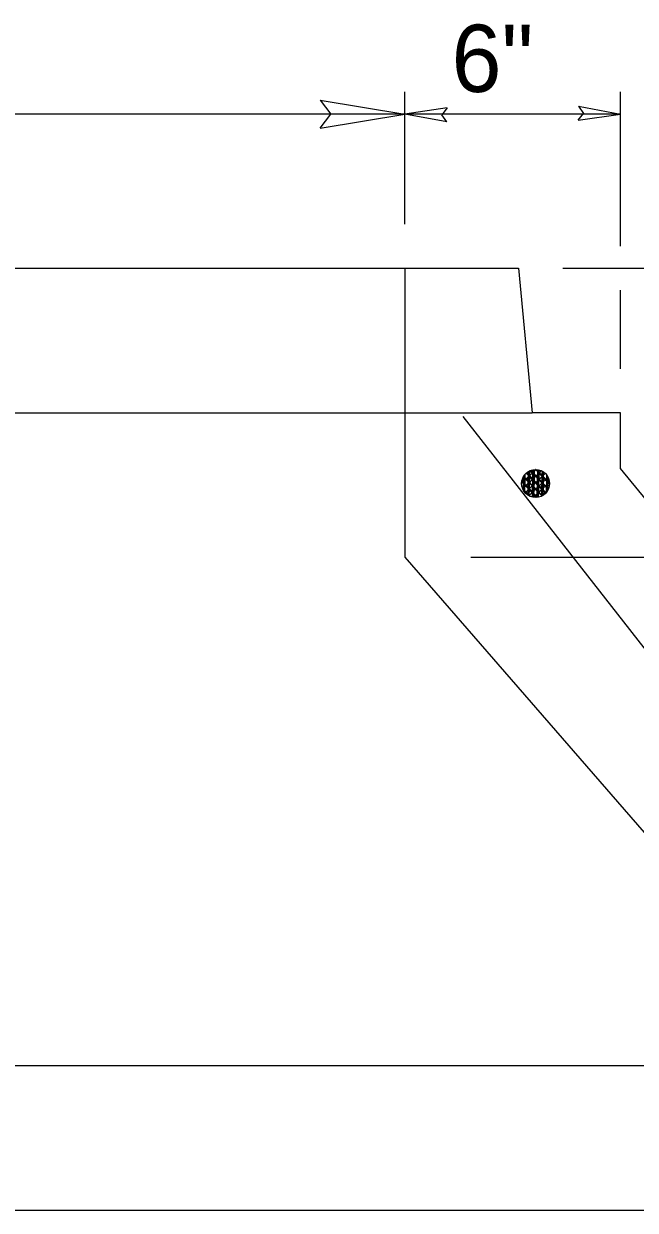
# Model space of a CAD drawing. Extents: x 26.41 to 33.74, y 20.66 to 30.6.
# Drawn here: x 27.743 to 28.289, y 29.343 to 30.401 of the extents above; entities that cross this region are included whole.
import ezdxf

# ---------------------------------------------------------------- set-up
doc = ezdxf.new("R2010")
doc.units = 0
for name, color, linetype in [('DETL-DIMS', 7, 'Continuous'), ('DETL-LINE', 7, 'Continuous'), ('DETL-NOTE', 7, 'Continuous')]:
    doc.layers.add(name, color=color, linetype=linetype)

msp = doc.modelspace()

# ---------------------------------------------------------------- linework, layer by layer
at = {"layer": 'DETL-DIMS'}
for p, q in [((28.0833, 30.2225), (28.0833, 30.3404)), ((28.2759, 30.2028), (28.2759, 30.3404)), ((28.0079, 30.3332), (28.0833, 30.3207)), ((28.0079, 30.3332), (28.0173, 30.3206)), ((28.0833, 30.3207), (26.6789, 30.3207)), ((28.0079, 30.3081), (28.0833, 30.3207)), ((28.0079, 30.3081), (28.0173, 30.3206)), ((28.1212, 30.3263), (28.0833, 30.3207)), ((28.1209, 30.3137), (28.0833, 30.3207)), ((28.2759, 30.3207), (28.0833, 30.3207)), ((28.1212, 30.3263), (28.1163, 30.3201)), ((28.1209, 30.3137), (28.1163, 30.3201)), ((28.238, 30.3151), (28.2429, 30.3213)), ((28.238, 30.3151), (28.2759, 30.3207)), ((28.2383, 30.3277), (28.2759, 30.3207)), ((28.2383, 30.3277), (28.2429, 30.3213)), ((28.2243, 30.1831), (28.9392, 30.1831)), ((28.2759, 30.0936), (28.2759, 30.1635)), ((28.1423, 29.9254), (28.5719, 29.9254))]:
    msp.add_line(p, q, dxfattribs=at)
at = {"layer": 'DETL-LINE'}
for p, q in [((26.5968, 30.1831), (28.185, 30.1831)), ((28.0833, 30.1831), (28.0833, 29.9254)), ((28.185, 30.1831), (28.1971, 30.0543)), ((26.5847, 30.0543), (28.1971, 30.0543)), ((28.2759, 30.0543), (28.1971, 30.0543)), ((28.2759, 30.0046), (28.2759, 30.0543)), ((28.1351, 30.051), (28.562, 29.5056)), ((28.1988, 30.0021), (28.1893, 29.9929)), ((28.1935, 29.9876), (28.1937, 30.0008)), ((28.1947, 29.9876), (28.1949, 30.0008)), ((28.2047, 30.002), (28.1951, 29.9928)), ((28.2058, 29.9918), (28.1966, 30.0013)), ((28.2061, 29.9922), (28.1969, 30.0017)), ((28.1976, 29.9875), (28.1979, 30.0008)), ((28.1988, 29.9875), (28.199, 30.0007)), ((28.2017, 29.9874), (28.202, 30.0007)), ((28.2117, 29.9916), (28.2025, 30.0012)), ((28.2119, 29.9921), (28.2028, 30.0016)), ((28.2029, 29.9874), (28.2032, 30.0006)), ((28.2059, 29.9874), (28.2061, 30.0006)), ((28.2071, 29.9873), (28.2073, 30.0006)), ((28.6248, 29.5791), (28.2759, 30.0046)), ((28.1969, 29.9832), (28.1877, 29.9927)), ((28.1972, 29.9836), (28.188, 29.9931)), ((28.1987, 29.9963), (28.1892, 29.9871)), ((28.1905, 29.9835), (28.1907, 29.9968)), ((28.1999, 29.986), (28.1907, 29.9956)), ((28.2001, 29.9806), (28.1909, 29.9902)), ((28.2002, 29.9865), (28.191, 29.996)), ((28.2016, 29.9933), (28.192, 29.9841)), ((28.2017, 29.9991), (28.1921, 29.99)), ((28.1934, 29.9835), (28.1937, 29.9967)), ((28.2027, 29.9831), (28.1935, 29.9926)), ((28.2028, 29.9889), (28.1937, 29.9984)), ((28.203, 29.9835), (28.1938, 29.993)), ((28.2032, 29.9893), (28.194, 29.9989)), ((28.1946, 29.9834), (28.1948, 29.9967)), ((28.2045, 29.9904), (28.1949, 29.9812)), ((28.2045, 29.9962), (28.195, 29.987)), ((28.2057, 29.9859), (28.1965, 29.9955)), ((28.2059, 29.9805), (28.1967, 29.9901)), ((28.206, 29.9864), (28.1968, 29.9959)), ((28.1975, 29.9834), (28.1978, 29.9966)), ((28.1975, 29.9793), (28.1977, 29.9925)), ((28.2074, 29.9932), (28.1979, 29.984)), ((28.2075, 29.999), (28.198, 29.9898)), ((28.1986, 29.9792), (28.1989, 29.9925)), ((28.1987, 29.9834), (28.199, 29.9966)), ((28.2086, 29.983), (28.1994, 29.9925)), ((28.2087, 29.9888), (28.1995, 29.9983)), ((28.2089, 29.9834), (28.1997, 29.9929)), ((28.209, 29.9892), (28.1998, 29.9988)), ((28.2102, 29.9902), (28.2007, 29.981)), ((28.2104, 29.996), (28.2008, 29.9869)), ((28.2016, 29.9792), (28.2018, 29.9924)), ((28.2017, 29.9833), (28.2019, 29.9966)), ((28.2028, 29.9833), (28.2031, 29.9965)), ((28.2028, 29.9791), (28.203, 29.9924)), ((28.2058, 29.9832), (28.206, 29.9965)), ((28.207, 29.9832), (28.2072, 29.9964)), ((28.1997, 29.9802), (28.1906, 29.9898)), ((28.2056, 29.9801), (28.1964, 29.9896)), ((28.0833, 29.9254), (28.432, 29.5245)), ((28.5284, 29.4719), (26.5935, 29.4719)), ((26.5042, 29.343), (28.6248, 29.343))]:
    msp.add_line(p, q, dxfattribs=at)
for points in [[(28.2, 29.9919), (28.1917, 30.0005)], [(28.1971, 29.9949), (28.1917, 30.0005)], [(28.1943, 29.9978), (28.1917, 30.0005)], [(28.2003, 29.9923), (28.1921, 30.0008)], [(28.1974, 29.9953), (28.1921, 30.0008)], [(28.1946, 29.9983), (28.1921, 30.0008)], [(28.2005, 30.0037), (28.1922, 29.9958)], [(28.1936, 29.9917), (28.1938, 30.002)], [(28.1937, 29.9959), (28.1938, 30.002)], [(28.1937, 30), (28.1938, 30.002)], [(28.1948, 29.9917), (28.1949, 30.0026)], [(28.1948, 29.9958), (28.1949, 30.0026)], [(28.1949, 29.9999), (28.1949, 30.0026)], [(28.2005, 30.0037), (28.1952, 29.9987)], [(28.2029, 29.9948), (28.1953, 30.0027)], [(28.2001, 29.9977), (28.1953, 30.0027)], [(28.1972, 30.0007), (28.1953, 30.0027)], [(28.2032, 29.9952), (28.1958, 30.003)], [(28.2004, 29.9982), (28.1958, 30.003)], [(28.1975, 30.0011), (28.1958, 30.003)], [(28.1977, 29.9916), (28.1979, 30.0035)], [(28.1978, 29.9958), (28.1979, 30.0035)], [(28.1979, 29.9999), (28.1979, 30.0035)], [(28.2052, 30.0026), (28.1981, 29.9957)], [(28.1989, 29.9916), (28.1991, 30.0037)], [(28.199, 29.9957), (28.1991, 30.0037)], [(28.199, 29.9999), (28.1991, 30.0037)], [(28.2088, 29.9946), (28.2001, 30.0037)], [(28.2059, 29.9976), (28.2001, 30.0037)], [(28.203, 30.0006), (28.2001, 30.0037)], [(28.2002, 30.0036), (28.2001, 30.0037)], [(28.2091, 29.9951), (28.2008, 30.0037)], [(28.2062, 29.9981), (28.2008, 30.0037)], [(28.2034, 30.001), (28.2008, 30.0037)], [(28.2018, 29.9916), (28.202, 30.0035)], [(28.2019, 29.9957), (28.202, 30.0035)], [(28.202, 29.9998), (28.202, 30.0035)], [(28.203, 29.9915), (28.2032, 30.0033)], [(28.203, 29.9957), (28.2032, 30.0033)], [(28.2031, 29.9998), (28.2032, 30.0033)], [(28.206, 29.9915), (28.2062, 30.0021)], [(28.206, 29.9956), (28.2062, 30.0021)], [(28.2061, 29.9997), (28.2062, 30.0021)], [(28.2071, 29.9915), (28.2073, 30.0014)], [(28.2072, 29.9956), (28.2073, 30.0014)], [(28.2073, 29.9997), (28.2073, 30.0014)], [(28.1959, 29.9992), (28.1876, 29.9913)], [(28.1929, 29.9964), (28.1876, 29.9913)], [(28.1899, 29.9935), (28.1876, 29.9913)], [(28.194, 29.9861), (28.1877, 29.9927)], [(28.1912, 29.9891), (28.1877, 29.9927)], [(28.1883, 29.9921), (28.1877, 29.9927)], [(28.1943, 29.9866), (28.1878, 29.9934)], [(28.1914, 29.9896), (28.1878, 29.9934)], [(28.1886, 29.9926), (28.1878, 29.9934)], [(28.1957, 29.9934), (28.1885, 29.9865)], [(28.1927, 29.9905), (28.1885, 29.9865)], [(28.197, 29.989), (28.1891, 29.9972)], [(28.1942, 29.992), (28.1891, 29.9972)], [(28.1913, 29.9949), (28.1891, 29.9972)], [(28.1893, 29.985), (28.1895, 29.9968)], [(28.1893, 29.985), (28.1894, 29.9927)], [(28.1894, 29.9877), (28.1896, 29.9979)], [(28.1894, 29.9918), (28.1896, 29.9979)], [(28.1973, 29.9894), (28.1894, 29.9977)], [(28.1944, 29.9924), (28.1894, 29.9977)], [(28.1916, 29.9954), (28.1894, 29.9977)], [(28.1895, 29.9959), (28.1896, 29.9979)], [(28.1905, 29.9876), (28.1907, 29.9995)], [(28.1905, 29.9833), (28.1906, 29.9926)], [(28.1906, 29.9918), (28.1907, 29.9995)], [(28.1907, 29.9959), (28.1907, 29.9995)], [(28.1986, 29.9905), (28.1908, 29.9829)], [(28.1934, 29.9808), (28.1936, 29.9926)], [(28.1945, 29.9801), (28.1948, 29.9926)], [(28.2087, 30.0002), (28.201, 29.9927)], [(28.2114, 29.986), (28.2024, 29.9954)], [(28.2093, 29.9829), (28.2025, 29.99)], [(28.2116, 29.9865), (28.2027, 29.9958)], [(28.2125, 29.9924), (28.2037, 29.9839)], [(28.2112, 29.9969), (28.2038, 29.9897)], [(28.2114, 29.986), (28.2052, 29.9924)], [(28.2125, 29.9908), (28.2053, 29.9982)], [(28.2116, 29.9865), (28.2055, 29.9928)], [(28.2125, 29.9915), (28.2056, 29.9986)], [(28.2057, 29.9801), (28.206, 29.9924)], [(28.2125, 29.9924), (28.2067, 29.9868)], [(28.2069, 29.9808), (28.2071, 29.9923)], [(28.2125, 29.9908), (28.2082, 29.9953)], [(28.2125, 29.9915), (28.2085, 29.9957)], [(28.2099, 29.9836), (28.2102, 29.9964)], [(28.2099, 29.9836), (28.2101, 29.9923)], [(28.21, 29.9873), (28.2102, 29.9985)], [(28.2101, 29.9914), (28.2102, 29.9985)], [(28.2102, 29.9955), (28.2102, 29.9985)], [(28.2111, 29.9873), (28.2113, 29.9966)], [(28.2111, 29.9855), (28.2113, 29.9964)], [(28.2111, 29.9855), (28.2113, 29.9922)], [(28.2112, 29.9914), (28.2113, 29.9966)], [(28.2113, 29.9955), (28.2113, 29.9966)], [(28.1952, 29.9798), (28.1884, 29.9868)], [(28.1942, 29.9807), (28.1884, 29.9868)], [(28.1914, 29.9837), (28.1884, 29.9868)], [(28.1885, 29.9867), (28.1884, 29.9868)], [(28.1898, 29.9877), (28.1885, 29.9865)], [(28.1938, 29.9804), (28.1891, 29.9854)], [(28.1938, 29.9804), (28.1891, 29.9854)], [(28.1911, 29.9833), (28.1891, 29.9854)], [(28.1893, 29.985), (28.1894, 29.9885)], [(28.1905, 29.9833), (28.1905, 29.9885)], [(28.1938, 29.9804), (28.1905, 29.9839)], [(28.1956, 29.9876), (28.1908, 29.9829)], [(28.1926, 29.9847), (28.1908, 29.9829)], [(28.1952, 29.9798), (28.1908, 29.9843)], [(28.1938, 29.9804), (28.1933, 29.9809)], [(28.1934, 29.9808), (28.1935, 29.9885)], [(28.2011, 29.9788), (28.1935, 29.9868)], [(28.1952, 29.9798), (28.1937, 29.9813)], [(28.2017, 29.9789), (28.1938, 29.9872)], [(28.2015, 29.9875), (28.194, 29.9803)], [(28.1985, 29.9846), (28.194, 29.9803)], [(28.1955, 29.9817), (28.194, 29.9803)], [(28.1945, 29.9801), (28.1947, 29.9884)], [(28.2011, 29.9788), (28.1963, 29.9838)], [(28.2017, 29.9789), (28.1966, 29.9842)], [(28.1975, 29.9791), (28.1976, 29.9884)], [(28.2073, 29.9874), (28.1985, 29.9789)], [(28.2043, 29.9845), (28.1985, 29.9789)], [(28.2014, 29.9816), (28.1985, 29.9789)], [(28.1986, 29.9789), (28.1988, 29.9883)], [(28.2056, 29.9801), (28.1993, 29.9867)], [(28.2061, 29.9803), (28.1996, 29.9871)], [(28.2016, 29.9789), (28.2017, 29.9883)], [(28.209, 29.9825), (28.2023, 29.9895)], [(28.2028, 29.9791), (28.2029, 29.9883)], [(28.2057, 29.9801), (28.2059, 29.9882)], [(28.211, 29.9852), (28.2057, 29.9801)], [(28.2102, 29.9844), (28.2057, 29.9801)], [(28.2072, 29.9815), (28.2057, 29.9801)], [(28.211, 29.9852), (28.2066, 29.9809)], [(28.2069, 29.9808), (28.2071, 29.9882)], [(28.211, 29.9852), (28.2095, 29.9838)], [(28.2099, 29.9836), (28.21, 29.9881)], [(28.2111, 29.9855), (28.2112, 29.9881)]]:
    msp.add_lwpolyline(points, dxfattribs=at)
msp.add_circle((28.2001, 29.9912), 0.0125, dxfattribs=at)

# ---------------------------------------------------------------- texts
at = {"layer": 'DETL-NOTE'}
msp.add_text('6"', height=0.05998, dxfattribs=at).set_placement((28.1251, 30.3404))

doc.saveas('drawing.dxf')
